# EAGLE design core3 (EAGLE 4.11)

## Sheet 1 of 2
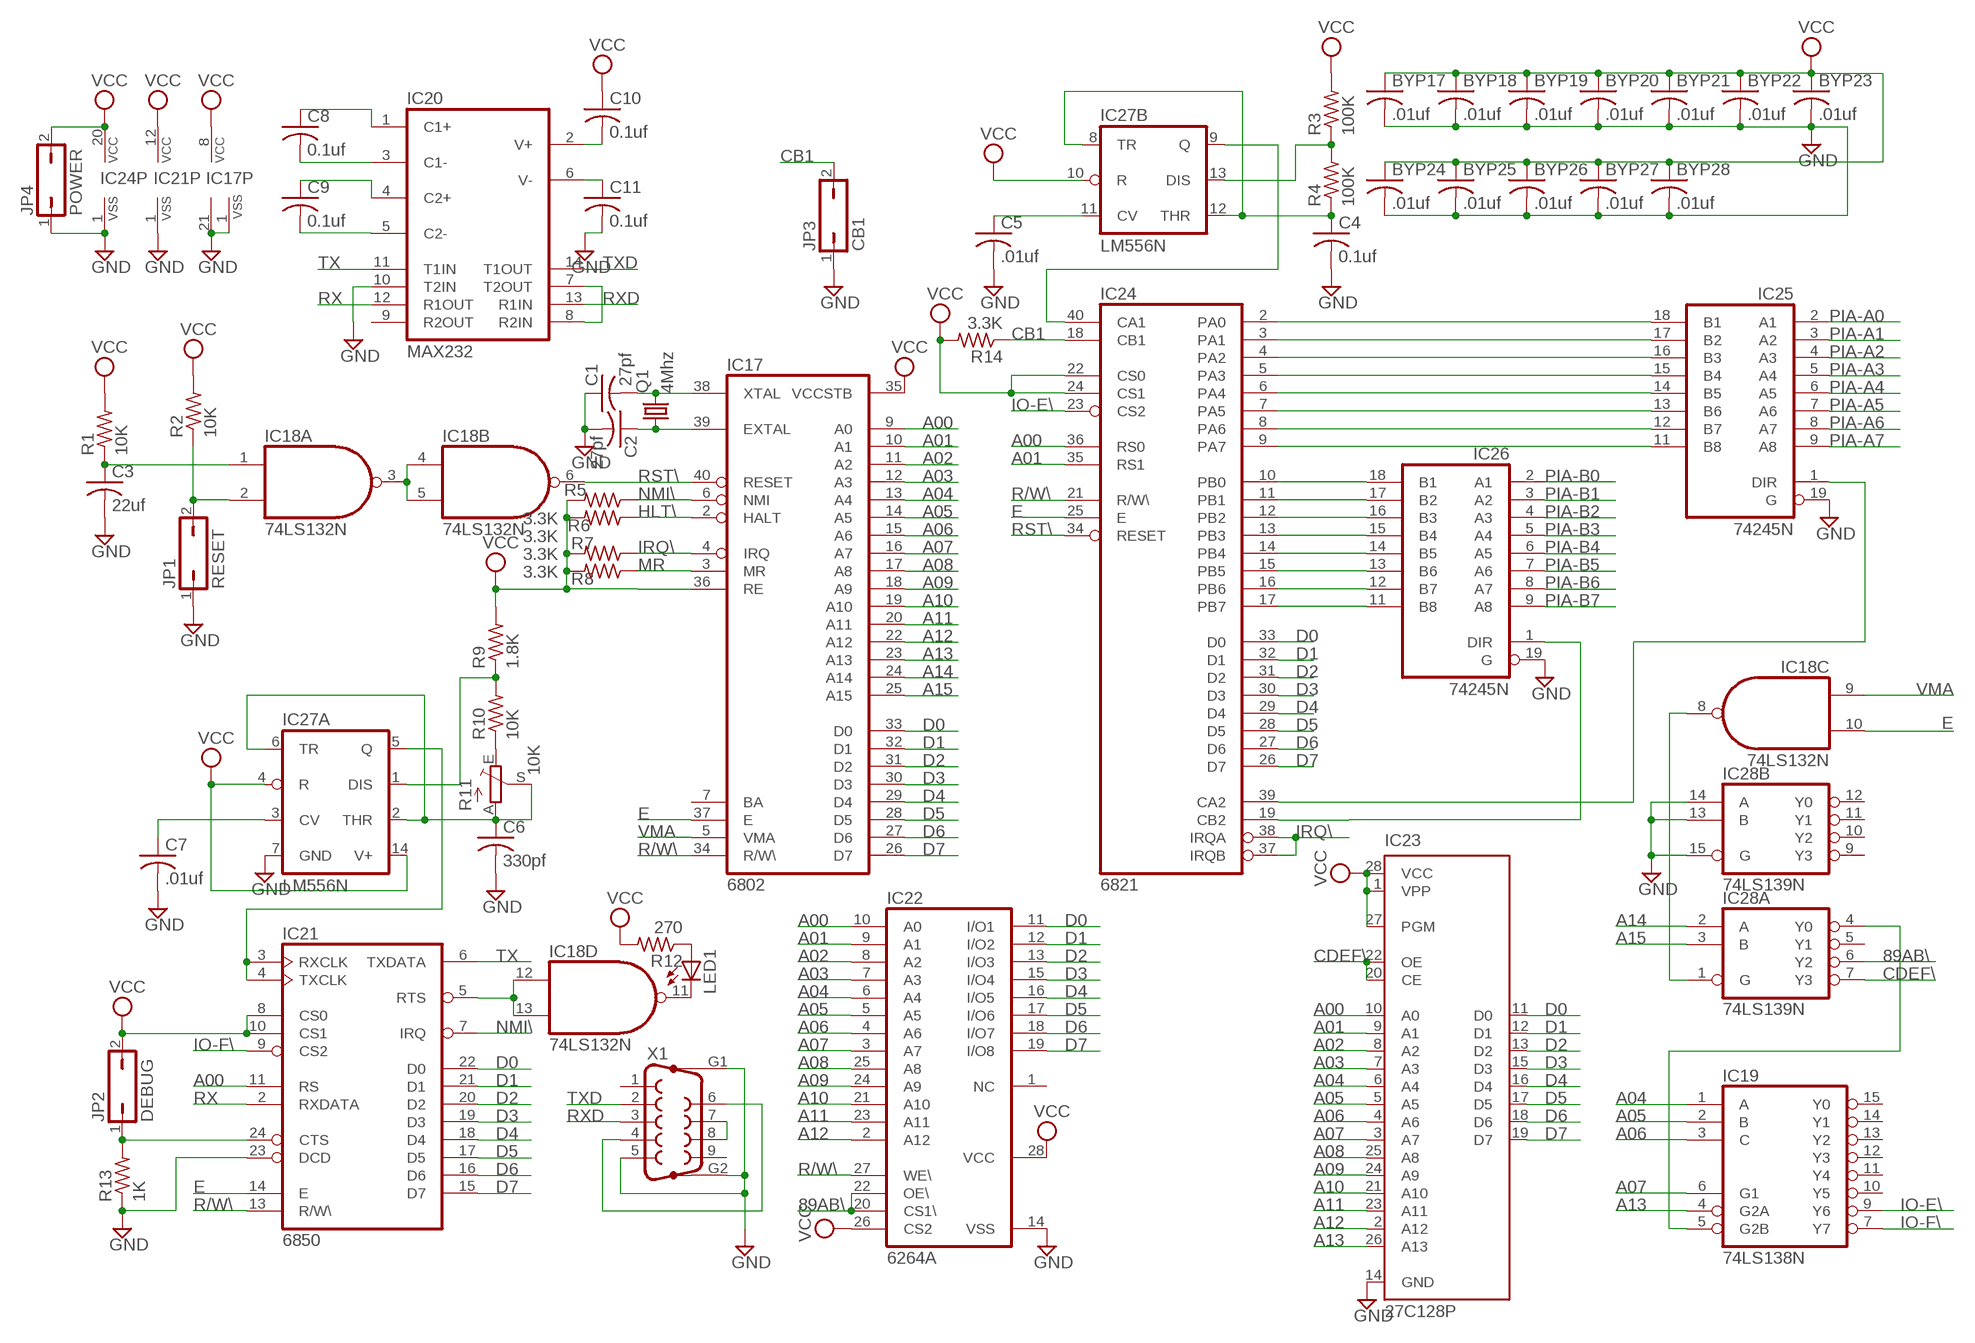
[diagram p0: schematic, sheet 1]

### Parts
BYP17  .01uf  C-US050-025X075  [C050-025X075]
BYP18  .01uf  C-US050-025X075  [C050-025X075]
BYP19  .01uf  C-US050-025X075  [C050-025X075]
BYP20  .01uf  C-US050-025X075  [C050-025X075]
BYP21  .01uf  C-US050-025X075  [C050-025X075]
BYP22  .01uf  C-US050-025X075  [C050-025X075]
BYP23  .01uf  C-US050-025X075  [C050-025X075]
BYP24  .01uf  C-US050-025X075  [C050-025X075]
BYP25  .01uf  C-US050-025X075  [C050-025X075]
BYP26  .01uf  C-US050-025X075  [C050-025X075]
BYP27  .01uf  C-US050-025X075  [C050-025X075]
BYP28  .01uf  C-US050-025X075  [C050-025X075]
C1  27pf  C-US050-025X075  [C050-025X075]
C2  27pf  C-US050-025X075  [C050-025X075]
C3  22uf  C-US102-043X133  [C102-043X133]
C4  0.1uf  C-US050-025X075  [C050-025X075]
C5  .01uf  C-US050-025X075  [C050-025X075]
C6  330pf  C-US050-025X075  [C050-025X075]
C7  .01uf  C-US050-025X075  [C050-025X075]
C8  0.1uf  C-US050-025X075  [C050-025X075]
C9  0.1uf  C-US050-025X075  [C050-025X075]
C10  0.1uf  C-US050-025X075  [C050-025X075]
C11  0.1uf  C-US050-025X075  [C050-025X075]
IC17  6802  [DIL40]
IC18  74LS132N  74LS00N  [DIL14]
IC19  74LS138N  [DIL16]
IC20  MAX232  [DIL16]
IC21  6850  [DIL24]
IC22  6264A  [DIL28-6]
IC23  27C128P  [DIL28-6]
IC24  6821  [DIL40]
IC25  74245N  74LS245N  [DIL20]
IC26  74245N  74LS245N  [DIL20]
IC27  LM556N  [DIL14]
IC28  74LS139N  [DIL16]
JP1  RESET  JP1Q  [JP1]
JP2  DEBUG  JP1Q  [JP1]
JP3  CB1  JP1Q  [JP1]
JP4  POWER  JP1Q  [JP1]
LED1  LED3MM  [LED3MM]
Q1  4Mhz  CRYTALHC18U-V  [HC18U-V]
R1  10K  R-US_0207/7  [0207/7]
R2  10K  R-US_0207/7  [0207/7]
R3  100K  R-US_0207/7  [0207/7]
R4  100K  R-US_0207/7  [0207/7]
R5  3.3K  R-US_0207/7  [0207/7]
R6  3.3K  R-US_0207/7  [0207/7]
R7  3.3K  R-US_0207/7  [0207/7]
R8  3.3K  R-US_0207/7  [0207/7]
R9  1.8K  R-US_0207/7  [0207/7]
R10  10K  R-US_0207/7  [0207/7]
R11  10K  TRIM_EU-B90P  [SP19L]
R12  270  R-US_0207/7  [0207/7]
R13  1K  R-US_0207/7  [0207/7]
R14  3.3K  R-US_0207/7  [0207/7]
X1  F09HP  [F09HP]

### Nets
89AB\: IC22.20(CS1\) IC22.22(OE\) IC28.6(A:Y2)
A00: IC17.9(A0) IC21.11(RS) IC22.10(A0) IC23.10(A0) IC24.36(RS0)
A01: IC17.10(A1) IC22.9(A1) IC23.9(A1) IC24.35(RS1)
A02: IC17.11(A2) IC22.8(A2) IC23.8(A2)
A03: IC17.12(A3) IC22.7(A3) IC23.7(A3)
A04: IC17.13(A4) IC19.1(A) IC22.6(A4) IC23.6(A4)
A05: IC17.14(A5) IC19.2(B) IC22.5(A5) IC23.5(A5)
A06: IC17.15(A6) IC19.3(C) IC22.4(A6) IC23.4(A6)
A07: IC17.16(A7) IC19.6(G1) IC22.3(A7) IC23.3(A7)
A08: IC17.17(A8) IC22.25(A8) IC23.25(A8)
A09: IC17.18(A9) IC22.24(A9) IC23.24(A9)
A10: IC17.19(A10) IC22.21(A10) IC23.21(A10)
A11: IC17.20(A11) IC22.23(A11) IC23.23(A11)
A12: IC17.22(A12) IC22.2(A12) IC23.2(A12)
A13: IC17.23(A13) IC19.4(G2A) IC23.26(A13)
A14: IC17.24(A14) IC28.2(A:A)
A15: IC17.25(A15) IC28.3(A:B)
CB1: IC24.18(CB1) JP3.2 R14.1
CDEF\: IC23.20(CE) IC23.22(OE) IC28.7(A:Y3)
D0: IC17.33(D0) IC21.22(D0) IC22.11(I/O1) IC23.11(D0) IC24.33(D0)
D1: IC17.32(D1) IC21.21(D1) IC22.12(I/O2) IC23.12(D1) IC24.32(D1)
D2: IC17.31(D2) IC21.20(D2) IC22.13(I/O3) IC23.13(D2) IC24.31(D2)
D3: IC17.30(D3) IC21.19(D3) IC22.15(I/O4) IC23.15(D3) IC24.30(D3)
D4: IC17.29(D4) IC21.18(D4) IC22.16(I/O5) IC23.16(D4) IC24.29(D4)
D5: IC17.28(D5) IC21.17(D5) IC22.17(I/O6) IC23.17(D5) IC24.28(D5)
D6: IC17.27(D6) IC21.16(D6) IC22.18(I/O7) IC23.18(D6) IC24.27(D6)
D7: IC17.26(D7) IC21.15(D7) IC22.19(I/O8) IC23.19(D7) IC24.26(D7)
E: IC17.37(E) IC18.10(C:I1) IC21.14(E) IC24.25(E)
GND [Power]: BYP17.2 BYP18.2 BYP19.2 BYP20.2 BYP21.2 BYP22.2 BYP23.2 BYP24.2 BYP25.2 BYP26.2 BYP27.2 BYP28.2 C1.1 C2.2 C3.2 C4.2 C5.2 C6.2 C7.2 C11.2 IC17.1(VSS) IC17.21(VSS) IC20.10(T2IN) IC21.1(VSS) IC21.23(DCD) IC22.14(VSS) IC23.14(GND) IC24.1(VSS) IC25.19(G) IC26.19(G) IC27.7(A:GND) IC28.13(B:B) IC28.14(B:A) IC28.15(B:G) JP1.1 JP3.1 JP4.1 R13.1 X1.5 X1.G1 X1.G2 ; also sheet 2
HLT\: IC17.2(HALT) R5.1
IO-E\: IC19.9(Y6) IC24.23(CS2)
IO-F\: IC19.7(Y7) IC21.9(CS2)
IRQ\: IC17.4(IRQ) IC24.37(IRQB) IC24.38(IRQA) R7.1
MR: IC17.3(MR) R8.1
N$3: C2.1 IC17.39(EXTAL) Q1.1
N$4: C1.2 IC17.38(XTAL) Q1.2
N$5: IC24.2(PA0) IC25.18(B1)
N$6: IC18.3(A:O) IC18.4(B:I0) IC18.5(B:I1)
N$21: C3.1 IC18.1(A:I0) R1.1
N$22: IC18.2(A:I1) JP1.2 R2.1
N$23: IC21.3(RXCLK) IC21.4(TXCLK) IC27.5(A:Q)
N$24: IC24.10(PB0) IC26.18(B1)
N$25: IC24.11(PB1) IC26.17(B2)
N$27: C6.1 IC27.2(A:THR) IC27.6(A:TR) R11.A R11.S
N$28: IC27.1(A:DIS) R9.1 R10.2
N$94: IC24.12(PB2) IC26.16(B3)
N$124: IC24.13(PB3) IC26.15(B4)
N$125: IC24.14(PB4) IC26.14(B5)
N$126: IC24.15(PB5) IC26.13(B6)
N$127: IC24.16(PB6) IC26.12(B7)
N$128: IC24.17(PB7) IC26.11(B8)
N$129: IC24.3(PA1) IC25.17(B2)
N$130: IC24.4(PA2) IC25.16(B3)
N$131: IC24.5(PA3) IC25.15(B4)
N$132: IC24.6(PA4) IC25.14(B5)
N$133: IC24.7(PA5) IC25.13(B6)
N$134: IC24.8(PA6) IC25.12(B7)
N$135: IC24.9(PA7) IC25.11(B8)
N$136: IC24.19(CB2) IC26.1(DIR)
N$137: IC24.39(CA2) IC25.1(DIR)
N$138: IC24.40(CA1) IC27.9(B:Q)
N$140: C4.1 IC27.8(B:TR) IC27.12(B:THR) R4.1
N$141: IC27.13(B:DIS) R3.1 R4.2
N$142: C5.1 IC27.11(B:CV)
N$143: R10.1 R11.E
N$144: X1.4 X1.6
N$145: X1.7 X1.8
N$147: IC18.12(D:I0) IC18.13(D:I1) IC21.5(RTS)
N$148: IC18.11(D:O) LED1.K(C)
N$149: LED1.A R12.1
N$150: IC21.24(CTS) JP2.1 R13.2
N$151: IC18.8(C:O) IC28.1(A:G)
N$152: IC19.5(G2B) IC28.4(A:Y0)
N$153: IC20.7(T2OUT) IC20.8(R2IN)
N$154: C7.1 IC27.3(A:CV)
N$155: C9.2 IC20.5(C2-)
N$156: C9.1 IC20.4(C2+)
N$157: C8.2 IC20.3(C1-)
N$158: C8.1 IC20.1(C1+)
N$159: C11.1 IC20.6(V-)
N$160: C10.2 IC20.2(V+)
NMI\: IC17.6(NMI) IC21.7(IRQ) R6.1
PIA-A0: IC25.2(A1) ; also sheet 2
PIA-A1: IC25.3(A2) ; also sheet 2
PIA-A2: IC25.4(A3) ; also sheet 2
PIA-A3: IC25.5(A4) ; also sheet 2
PIA-A4: IC25.6(A5) ; also sheet 2
PIA-A5: IC25.7(A6) ; also sheet 2
PIA-A6: IC25.8(A7) ; also sheet 2
PIA-A7: IC25.9(A8) ; also sheet 2
PIA-B0: IC26.2(A1) ; also sheet 2
PIA-B1: IC26.3(A2) ; also sheet 2
PIA-B2: IC26.4(A3) ; also sheet 2
PIA-B3: IC26.5(A4) ; also sheet 2
PIA-B4: IC26.6(A5) ; also sheet 2
PIA-B5: IC26.7(A6) ; also sheet 2
PIA-B6: IC26.8(A7) ; also sheet 2
PIA-B7: IC26.9(A8) ; also sheet 2
R/W\: IC17.34(R/W\) IC21.13(R/W\) IC22.27(WE\) IC24.21(R/W\)
RST\: IC17.40(RESET) IC18.6(B:O) IC24.34(RESET)
RX: IC20.12(R1OUT) IC21.2(RXDATA)
RXD: IC20.13(R1IN) X1.3
TX: IC20.11(T1IN) IC21.6(TXDATA)
TXD: IC20.14(T1OUT) X1.2
VCC [Power]: BYP17.1 BYP18.1 BYP19.1 BYP20.1 BYP21.1 BYP22.1 BYP23.1 BYP24.1 BYP25.1 BYP26.1 BYP27.1 BYP28.1 C10.1 IC17.8(VCC) IC17.35(VCCSTB) IC17.36(RE) IC21.8(CS0) IC21.10(CS1) IC21.12(VCC) IC22.26(CS2) IC22.28(VCC) IC23.1(VPP) IC23.27(PGM) IC23.28(VCC) IC24.20(VCC) IC24.22(CS0) IC24.24(CS1) IC27.4(A:R) IC27.10(B:R) IC27.14(A:V+) JP2.2 JP4.2 R1.2 R2.2 R3.2 R5.2 R6.2 R7.2 R8.2 R9.2 R12.2 R14.2 ; also sheet 2
VMA: IC17.5(VMA) IC18.9(C:I0)
Unconnected: IC17.7(BA) IC19.10(Y5) IC19.11(Y4) IC19.12(Y3) IC19.13(Y2) IC19.14(Y1) IC19.15(Y0) IC20.9(R2OUT) IC22.1(NC) IC28.5(A:Y1) IC28.9(B:Y3) IC28.10(B:Y2) IC28.11(B:Y1) IC28.12(B:Y0) X1.1 X1.9

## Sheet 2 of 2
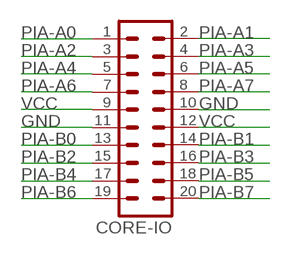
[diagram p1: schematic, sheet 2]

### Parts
CORE-IO  MA10-2  [MA10-2]

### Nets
GND [Power]: CORE-IO.10 CORE-IO.11 ; also sheet 1
PIA-A0: CORE-IO.1 ; also sheet 1
PIA-A1: CORE-IO.2 ; also sheet 1
PIA-A2: CORE-IO.3 ; also sheet 1
PIA-A3: CORE-IO.4 ; also sheet 1
PIA-A4: CORE-IO.5 ; also sheet 1
PIA-A5: CORE-IO.6 ; also sheet 1
PIA-A6: CORE-IO.7 ; also sheet 1
PIA-A7: CORE-IO.8 ; also sheet 1
PIA-B0: CORE-IO.13 ; also sheet 1
PIA-B1: CORE-IO.14 ; also sheet 1
PIA-B2: CORE-IO.15 ; also sheet 1
PIA-B3: CORE-IO.16 ; also sheet 1
PIA-B4: CORE-IO.17 ; also sheet 1
PIA-B5: CORE-IO.18 ; also sheet 1
PIA-B6: CORE-IO.19 ; also sheet 1
PIA-B7: CORE-IO.20 ; also sheet 1
VCC [Power]: CORE-IO.9 CORE-IO.12 ; also sheet 1

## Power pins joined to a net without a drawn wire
GND: IC18.7(P:GND) IC19.8(GND) IC20.15(GND) IC25.10(GND) IC26.10(GND) IC28.8(P:GND)
VCC: IC18.14(P:VCC) IC19.16(VCC) IC20.16(VCC) IC25.20(VCC) IC26.20(VCC) IC28.16(P:VCC)

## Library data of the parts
BYP17-BYP28 C1-C11 = rcl:C-US: CAPACITOR, American symbol
CORE-IO = con-lstb:MA10-2: PIN HEADER
IC17 = micro-motorola:6802: MICROCONTROLLER/MEMORY DEVICE
IC18 = 74xx-us:74*00: Quad 2-input NAND gate
IC19 = 74xx-us:74*138: 3-line to 8-line DECODER/DEMULTIPLEXER
IC20 = maxim:MAX232: RS232 TRANSEIVER
IC21 = micro-motorola:6850: MICROCONTROLLER/MEMORY DEVICE
IC22 = memory-hitachi:6264A: MEMORY
IC23 = microchip:27*128: CMOS EPROM 128 K (16 K x 8)
IC24 = micro-motorola:6821: MICROCONTROLLER/MEMORY DEVICE
IC25 IC26 = 74xx-us:74*245: Octal BUS TRANSCEIVER, 3-state
IC27 = linear:*556: Dual TIMER
IC28 = 74xx-us:74*139: Dual 2-line to 4-line DECODER/DEMULTIPLEXER
JP1-JP4 = jumper:JP1Q: JUMPER
LED1 = led:LED: LED
Q1 = crystal:CRYTAL: CRYSTAL
R1-R10 R12-R14 = rcl:R-US_: RESISTOR, American symbol
R11 = pot:TRIM_EU-: POTENTIOMETER
X1 = con-subd:F09HP: SUB-D

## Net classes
1 Power: width 0.508 mm, drill 0.254 mm, clearance 0.254 mm

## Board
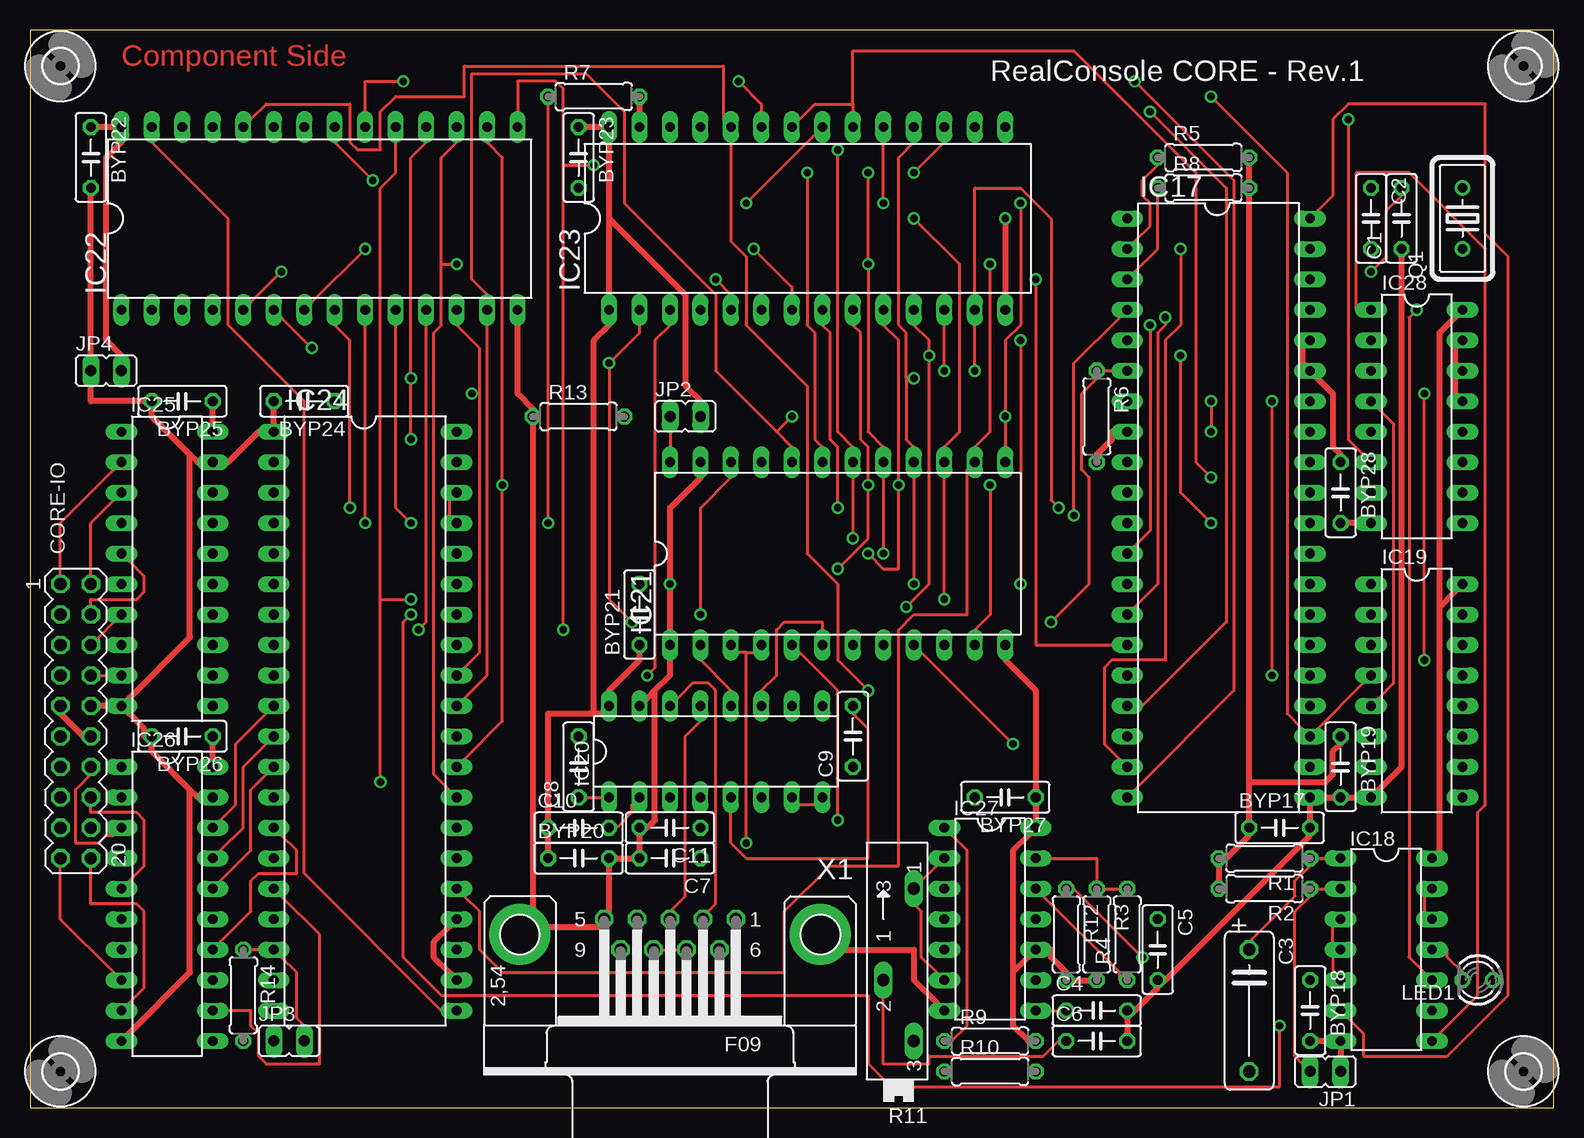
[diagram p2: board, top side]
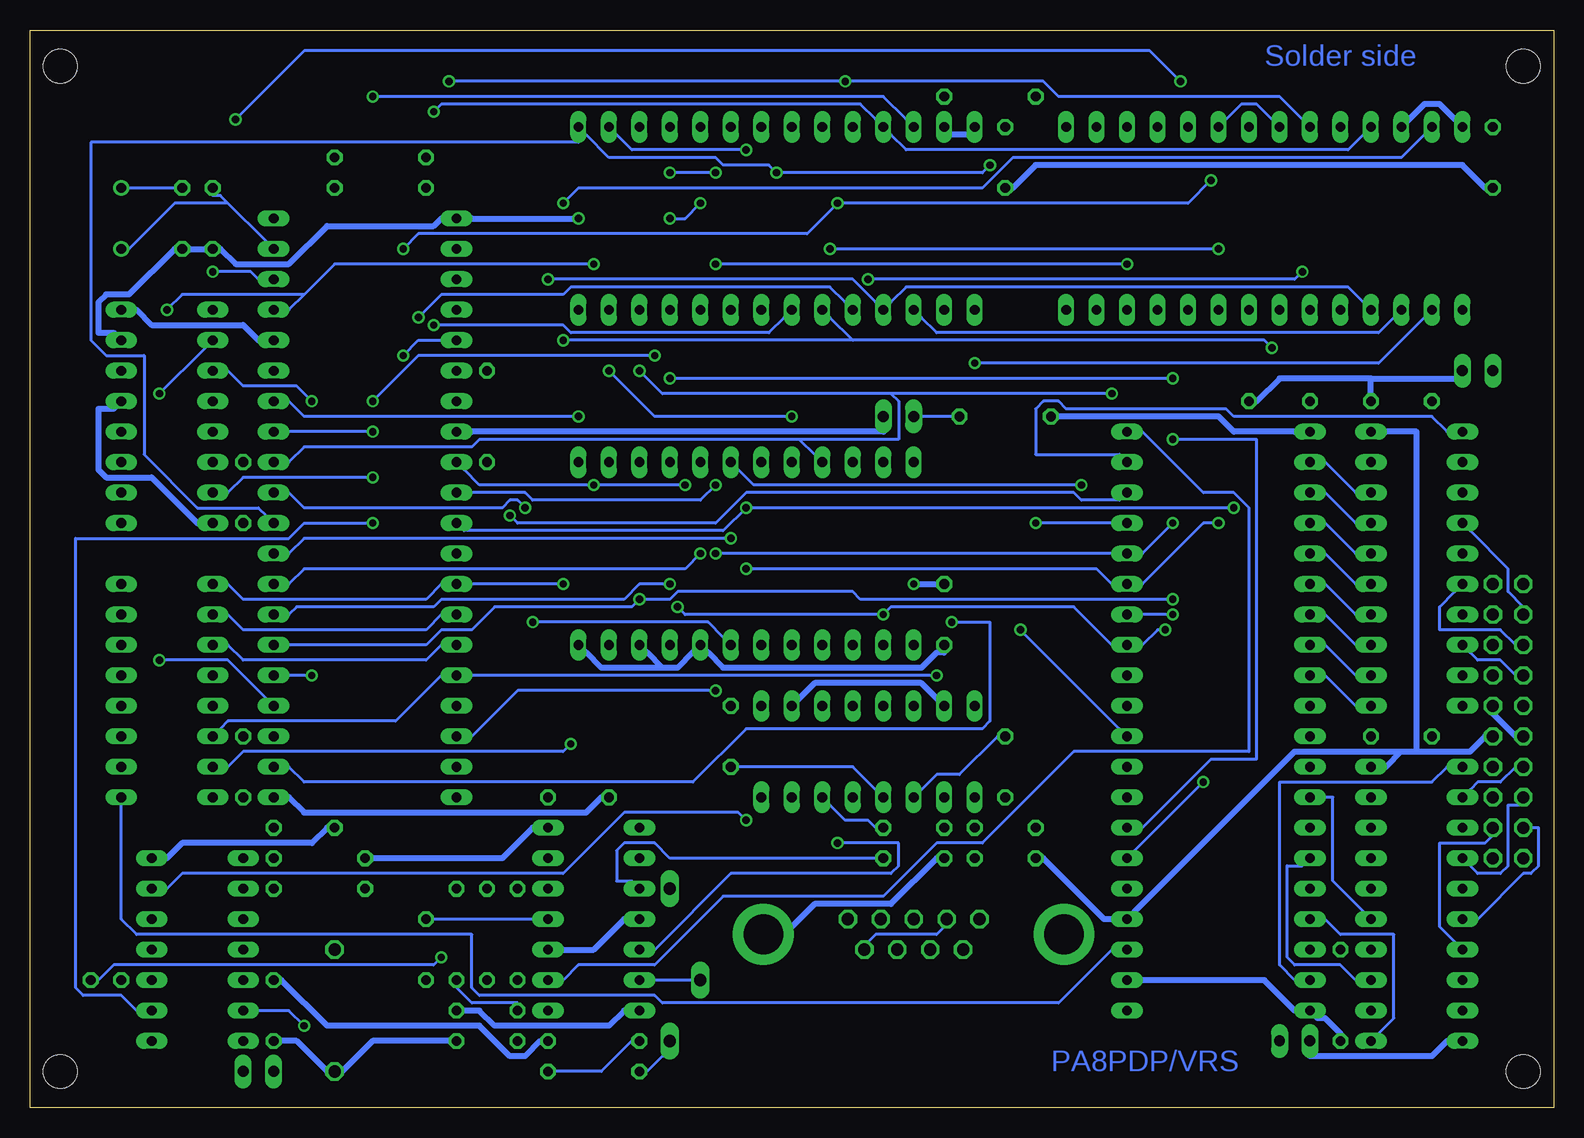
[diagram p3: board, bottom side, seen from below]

Size 126.98 x 89.84 mm. Coordinates in mm from the lower left corner, seen from the top.
Outline: 0,0 126.98,0 126.98,89.84 0,89.84 0,0
Copper layers (1*16): Top 0.035mm / dielectric 1.5mm / Bottom 0.035mm
Design rules "olimex10mil": minimum track width 10mil, minimum drill 24mil, track to track 10mil, track to pad 10mil, pad to pad 10mil, via to via 10mil, smd to smd 10mil, copper to edge 40mil, drill to drill 10mil, minimum pad ring 10mil, minimum via ring 8mil, stop-mask expansion 0mil, vias tented up to drill 0mil, thermal gap 10mil

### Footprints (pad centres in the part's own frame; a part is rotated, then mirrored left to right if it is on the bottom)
C050-025X075 = drill 0.813 octagon: 1 -2.54,0; 2 2.54,0
C102-043X133 = drill 1.016 octagon: 1 -5.08,0; 2 5.08,0
MA10-2 = drill 1.016 octagon: 1 -11.43,-1.27; 2 -11.43,1.27; 3 -8.89,-1.27; 4 -8.89,1.27; 5 -6.35,-1.27; 6 -6.35,1.27; 7 -3.81,-1.27; 8 -3.81,1.27; 9 -1.27,-1.27; 10 -1.27,1.27; 11 1.27,-1.27; 12 1.27,1.27; 13 3.81,-1.27; 14 3.81,1.27; 15 6.35,-1.27; 16 6.35,1.27; 17 8.89,-1.27; 18 8.89,1.27; 19 11.43,-1.27; 20 11.43,1.27
DIL40 = drill 0.813 long: 1 -24.13,-7.62; 2 -21.59,-7.62; 3 -19.05,-7.62; 4 -16.51,-7.62; 5 -13.97,-7.62; 6 -11.43,-7.62; 7 -8.89,-7.62; 8 -6.35,-7.62; 9 -3.81,-7.62; 10 -1.27,-7.62; 11 1.27,-7.62; 12 3.81,-7.62; 13 6.35,-7.62; 14 8.89,-7.62; 15 11.43,-7.62; 16 13.97,-7.62; 17 16.51,-7.62; 18 19.05,-7.62; 19 21.59,-7.62; 20 24.13,-7.62; 21 24.13,7.62; 22 21.59,7.62; 23 19.05,7.62; 24 16.51,7.62; 25 13.97,7.62; 26 11.43,7.62; 27 8.89,7.62; 28 6.35,7.62; 29 3.81,7.62; 30 1.27,7.62; 31 -1.27,7.62; 32 -3.81,7.62; 33 -6.35,7.62; 34 -8.89,7.62; 35 -11.43,7.62; 36 -13.97,7.62; 37 -16.51,7.62; 38 -19.05,7.62; 39 -21.59,7.62; 40 -24.13,7.62
DIL14 = drill 0.813 long: 1 -7.62,-3.81; 2 -5.08,-3.81; 3 -2.54,-3.81; 4 0,-3.81; 5 2.54,-3.81; 6 5.08,-3.81; 7 7.62,-3.81; 8 7.62,3.81; 9 5.08,3.81; 10 2.54,3.81; 11 0,3.81; 12 -2.54,3.81; 13 -5.08,3.81; 14 -7.62,3.81
DIL16 = drill 0.813 long: 1 -8.89,-3.81; 2 -6.35,-3.81; 3 -3.81,-3.81; 4 -1.27,-3.81; 5 1.27,-3.81; 6 3.81,-3.81; 7 6.35,-3.81; 8 8.89,-3.81; 9 8.89,3.81; 10 6.35,3.81; 11 3.81,3.81; 12 1.27,3.81; 13 -1.27,3.81; 14 -3.81,3.81; 15 -6.35,3.81; 16 -8.89,3.81
DIL24 = drill 0.813 long: 1 -13.97,-7.62; 2 -11.43,-7.62; 3 -8.89,-7.62; 4 -6.35,-7.62; 5 -3.81,-7.62; 6 -1.27,-7.62; 7 1.27,-7.62; 8 3.81,-7.62; 9 6.35,-7.62; 10 8.89,-7.62; 11 11.43,-7.62; 12 13.97,-7.62; 13 13.97,7.62; 14 11.43,7.62; 15 8.89,7.62; 16 6.35,7.62; 17 3.81,7.62; 18 1.27,7.62; 19 -1.27,7.62; 20 -3.81,7.62; 21 -6.35,7.62; 22 -8.89,7.62; 23 -11.43,7.62; 24 -13.97,7.62
DIL28-6 = drill 0.813 long: 1 -16.51,-7.62; 2 -13.97,-7.62; 3 -11.43,-7.62; 4 -8.89,-7.62; 5 -6.35,-7.62; 6 -3.81,-7.62; 7 -1.27,-7.62; 8 1.27,-7.62; 9 3.81,-7.62; 10 6.35,-7.62; 11 8.89,-7.62; 12 11.43,-7.62; 13 13.97,-7.62; 14 16.51,-7.62; 15 16.51,7.62; 16 13.97,7.62; 17 11.43,7.62; 18 8.89,7.62; 19 6.35,7.62; 20 3.81,7.62; 21 1.27,7.62; 22 -1.27,7.62; 23 -3.81,7.62; 24 -6.35,7.62; 25 -8.89,7.62; 26 -11.43,7.62; 27 -13.97,7.62; 28 -16.51,7.62
DIL20 = drill 0.813 long: 1 -11.43,-3.81; 2 -8.89,-3.81; 3 -6.35,-3.81; 4 -3.81,-3.81; 5 -1.27,-3.81; 6 1.27,-3.81; 7 3.81,-3.81; 8 6.35,-3.81; 9 8.89,-3.81; 10 11.43,-3.81; 11 11.43,3.81; 12 8.89,3.81; 13 6.35,3.81; 14 3.81,3.81; 15 1.27,3.81; 16 -1.27,3.81; 17 -3.81,3.81; 18 -6.35,3.81; 19 -8.89,3.81; 20 -11.43,3.81
JP1 = drill 0.914 long: 1 0,-1.27; 2 0,1.27
LED3MM = drill 0.813 octagon: A -1.27,0; K 1.27,0
HC18U-V = drill 0.813 round: 1 -2.54,0; 2 2.54,0
0207/7 = drill 0.813 octagon: 1 -3.81,0; 2 3.81,0
SP19L = drill 1.016 long: A 5.715,-1.27; E -6.985,-1.27; S -1.905,1.27
2,8 = hole 2.8: 0,0
F09HP = drill 1.016 octagon: 1 -5.486,-1.27; 2 -2.743,-1.27; 3 0,-1.27; 4 2.743,-1.27; 5 5.486,-1.27; 6 -4.115,1.27; 7 -1.372,1.27; 8 1.372,1.27; 9 4.115,1.27 | drill 3.302 pad 5.08 round: G1 -12.522,0; G2 12.522,0

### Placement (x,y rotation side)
BYP17  104.14,23.33 0 top
BYP18  106.68,8.09 270 top
BYP19  109.22,28.41 270 top
BYP20  45.71,20.79 0 top
BYP21  50.79,41.11 90 top
BYP22  5.08,79.21 270 top
BYP23  45.71,79.21 270 top
BYP24  22.86,58.89 180 top
BYP25  12.69,58.89 180 top
BYP26  12.69,30.95 180 top
BYP27  81.28,25.87 180 top
BYP28  109.22,51.27 270 top
C1  114.3,74.13 90 top
C2  111.76,74.13 270 top
C3  101.59,8.09 270 top
C4  88.9,8.09 0 top
C5  93.98,13.17 270 top
C6  88.9,5.55 0 top
C7  53.34,20.79 180 top
C8  45.71,28.41 90 top
C9  68.58,30.95 90 top
C10  45.71,23.33 0 top
C11  53.34,23.33 180 top
CORE-IO  3.81,32.22 270 top
IC17  99.06,50 270 top
IC18  113.03,13.17 270 top
IC19  115.56,34.76 270 top
IC20  57.14,29.68 0 top
IC21  67.31,46.19 0 top
IC22  24.12,74.13 0 top
IC23  64.77,74.13 0 top
IC24  27.94,32.22 270 top
IC25  11.42,44.92 270 top
IC26  11.42,16.98 270 top
IC27  80.01,15.71 270 top
IC28  115.56,57.62 270 top
JP1  107.95,3.01 90 top
JP2  54.6,57.62 270 top
JP3  21.59,5.55 270 top
JP4  6.34,61.43 270 top
LED1  120.65,10.63 180 top
Q1  119.38,74.13 90 top
R1  102.87,20.79 180 top
R2  102.87,18.25 180 top
R3  88.9,14.44 270 top
R4  91.44,14.44 90 top
R5  97.79,79.21 0 top
R6  88.9,57.62 270 top
R7  46.98,84.29 0 top
R8  97.79,76.67 0 top
R9  80.01,5.55 0 top
R10  80.01,3.01 0 top
R11  72.39,12.54 90 top
R12  86.36,14.44 270 top
R13  45.71,57.62 0 top
R14  17.78,9.36 270 top
U$3  [2,8]  2.54,86.83 0 top
U$4  [2,8]  2.54,3.01 0 top
U$5  [2,8]  124.45,86.83 0 top
U$6  [2,8]  124.45,3.01 0 top
X1  53.34,14.44 180 top

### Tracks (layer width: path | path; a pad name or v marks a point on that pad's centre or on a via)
89AB\  (via drill 0.61)
  Top 0.254: v109.85,82.39 109.85,55.71 111.12,54.45 IC28.6 | v31.11,85.56 27.94,85.56 27.94,83.02 IC22.20
  Bottom 0.254: IC22.22 23.49,82.39 24.76,83.66 26.03,83.66 27.3,82.39 IC22.20 | v109.85,82.39 104.14,88.1 33.65,88.1 v31.11,85.56
A00  (via drill 0.61)
  Top 0.254: v31.75,48.73 30.48,50 30.48,65.24 IC22.10 | v80.01,51.91 80.01,41.11 78.73,39.84 IC21.11 | IC23.10 71.12,65.24 72.39,63.97 v72.39,51.91 72.39,44.92 71.12,44.92 v69.84,46.19
  Bottom 0.254: v31.75,48.73 34.28,46.19 IC24.36 36.82,46.19 v69.84,46.19 | IC17.9 90.8,53.17 89.53,51.91 v80.01,51.91 v72.39,51.91
A01  (via drill 0.61)
  Top 0.254: v27.94,48.73 27.94,65.24 IC22.9 | IC23.9 68.58,65.24 69.21,64.61 69.21,55.71 69.84,55.08 v69.84,51.91 69.84,47.46 v67.31,44.92
  Bottom 0.254: v27.94,48.73 29.21,48.73 34.28,43.65 IC24.35 36.82,43.65 38.09,44.92 v67.31,44.92 | v69.84,51.91 71.12,50.63 85.09,50.63 85.72,51.27 90.17,51.27 IC17.10
A02  (via drill 0.61)
  Top 0.254: v26.67,50 26.67,63.97 25.39,65.24 IC22.8 | v67.31,50 67.31,55.08 66.67,55.71 66.67,64.61 66.04,65.24 IC23.8
  Bottom 0.254: v26.67,50 v67.31,50 69.21,48.09 90.8,48.09 IC17.11
A03  (via drill 0.61)
  Top 0.254: v27.94,71.59 23.49,67.14 IC22.7 | v60.32,71.59 63.49,68.41 63.49,67.78 IC23.7 | v93.34,65.24 93.34,48.09 92.07,46.82 IC17.12
  Bottom 0.254: v27.94,71.59 v60.32,71.59 | v93.34,65.24 82.55,65.24 81.91,64.61 65.4,64.61 64.13,65.88 IC23.7
A04  (via drill 0.61)
  Top 0.254: v23.49,63.34 20.95,65.88 IC22.6 | v82.55,63.97 v82.55,43.65
  Bottom 0.254: IC19.1 110.48,43.65 109.22,42.38 93.98,42.38 92.7,43.65 IC17.13 90.17,43.65 v82.55,43.65 | v23.49,63.34 24.12,63.97 58.41,63.97 | 58.41,63.97 60.32,65.88 IC23.6 | 58.41,63.97 v82.55,63.97
A05  (via drill 0.61)
  Top 0.254: v20.95,69.69 18.41,67.14 IC22.5 | v57.14,69.05 58.41,67.78 IC23.5 | v94.61,65.88 94.61,65.24 93.98,64.61 93.98,43.65 92.07,41.74 IC17.14
  Bottom 0.254: IC17.14 92.7,41.11 93.98,39.84 109.22,39.84 110.48,41.11 IC19.2 | v20.95,69.69 21.59,69.05 v57.14,69.05 | v94.61,65.88 92.7,67.78 82.55,67.78 81.91,68.41 60.32,68.41 59.05,67.14 IC23.5
A06  (via drill 0.61)
  Top 0.254: v83.81,69.05 83.81,38.57 90.17,38.57 IC17.15
  Bottom 0.254: IC17.15 92.7,38.57 93.98,37.3 109.22,37.3 110.48,38.57 IC19.3 | IC22.4 15.87,67.14 17.14,68.41 53.97,68.41 55.24,67.14 IC23.4 56.51,67.14 58.41,69.05 v83.81,69.05
A07  (via drill 0.61)
  Top 0.254: v51.43,36.03 52.06,36.66 52.06,63.97 53.34,65.24 IC23.3
  Bottom 0.254: IC19.6 111.12,31.58 110.48,32.22 96.52,32.22 92.7,36.03 IC17.16 90.17,36.03 v51.43,36.03 | IC22.3 13.33,65.88 14.6,64.61 51.43,64.61 52.7,65.88 IC23.3
A08  (via drill 0.61)
  Top 0.254: v93.34,83.02 99.69,76.67 99.69,40.48 92.7,33.49 IC17.17
  Bottom 0.254: IC22.25 15.87,81.11 17.14,79.84 53.97,79.84 55.24,81.11 IC23.25 56.51,82.39 57.78,83.66 92.7,83.66 v93.34,83.02
A09  (via drill 0.61)
  Top 0.254: IC22.24 18.41,82.39 19.68,83.66 26.67,83.66 26.67,80.48 27.3,79.84 29.21,79.84 29.21,83.02 30.48,84.29 36.19,84.29 36.19,86.83 57.78,86.83 57.78,82.39 IC23.24 58.41,80.48 58.41,72.22 59.68,70.95 59.68,65.24 64.77,60.16 64.77,46.19 67.31,43.65 67.31,37.3 v69.84,34.76
  Bottom 0.254: v69.84,34.76 86.36,34.76 90.17,30.95 IC17.18
A10  (via drill 0.61)
  Top 0.254: v28.57,77.3 25.39,80.48 IC22.21 | v59.68,75.4 65.4,81.11 IC23.21 | v95.88,71.59 95.88,65.24 94.61,63.97 94.61,37.3 90.17,37.3 89.53,36.66 89.53,30.31 90.8,29.04 IC17.19
  Bottom 0.254: v28.57,77.3 30.48,75.4 v59.68,75.4 62.22,72.86 94.61,72.86 v95.88,71.59
A11  (via drill 0.61)
  Top 0.254: v59.05,85.56 60.95,83.66 60.95,83.02 IC23.23 | v92.07,85.56 100.33,77.3 100.33,34.76 92.07,26.5 IC17.20
  Bottom 0.254: IC22.23 20.95,82.39 22.86,84.29 41.27,84.29 42.54,85.56 v59.05,85.56 v92.07,85.56
A12  (via drill 0.61)
  Top 0.254: IC23.2 50.79,65.24 50.79,64.61 v48.25,62.06 48.25,42.38 v50.16,40.48
  Bottom 0.254: v48.25,62.06 14.6,62.06 10.79,65.88 IC22.2 | v50.16,40.48 46.98,40.48 46.98,32.22 47.62,31.58 67.31,31.58 71.75,27.14 104.14,27.14 105.41,28.41 IC17.22
A13  (via drill 0.61)
  Top 0.254: v98.42,84.29 104.77,77.94 104.77,32.85 106.04,31.58 IC17.23 107.31,31.58 111.12,35.39 IC19.4
  Bottom 0.254: v98.42,84.29 55.88,84.29 53.97,82.39 IC23.26
A14  (via drill 0.61)
  Top 0.254: v116.2,37.3 v116.2,59.52
  Bottom 0.254: v116.2,37.3 110.48,37.3 107.31,34.12 IC17.24 | v116.2,59.52 112.39,63.34 IC28.2
A15  (via drill 0.61)
  Top 0.254: v103.5,36.03 v103.5,58.89
  Bottom 0.254: v103.5,36.03 105.41,36.03 IC17.25 | v103.5,58.89 104.77,60.16 109.22,60.16 110.48,61.43 IC28.3
CB1
  Top 0.254: R14.1 18.41,13.17 19.05,13.17 IC24.18 20.95,12.54 22.22,11.27 22.22,7.46 22.86,6.82 JP3.2
CDEF\  (via drill 0.61)
  Top 0.254: 68.58,83.66 65.4,83.66 64.13,82.39 IC23.22 | 68.58,83.66 68.58,83.02 IC23.20 | v98.42,52.54 97.15,53.81 97.15,77.94 86.99,88.1 68.58,88.1 68.58,83.66
  Bottom 0.254: v98.42,52.54 109.22,52.54 110.48,51.27 IC28.7
D0  (via drill 0.61)
  Top 0.254: v32.38,39.84 33.02,40.48 33.02,65.24 IC22.11 | v55.88,41.11 55.88,50 58.41,52.54 IC21.22 | v73.02,41.74 74.93,43.65 v74.93,62.7 74.93,63.97 73.66,65.24 IC23.11 | v98.42,58.89 v98.42,56.35
  Bottom 0.254: v32.38,39.84 33.02,39.84 34.28,38.57 IC24.33 36.82,38.57 40,41.74 55.24,41.74 v55.88,41.11 72.39,41.11 v73.02,41.74 | v98.42,56.35 105.41,56.35 IC17.33 | v98.42,58.89 94.61,62.7 v74.93,62.7
D1  (via drill 0.61)
  Top 0.254: 37.46,59.52 37.46,63.34 35.55,65.24 IC22.12 | 37.46,59.52 37.46,37.94 36.19,36.66 IC24.32 | v76.2,61.43 76.2,65.24 IC23.12 | 37.46,59.52 v36.82,59.52
  Bottom 0.254: 62.86,55.71 61.59,54.45 IC21.21 | 62.86,55.71 89.53,55.71 90.17,55.08 104.14,55.08 105.41,53.81 IC17.32 | v76.2,61.43 74.29,59.52 55.24,59.52 | 55.24,59.52 54.6,58.89 54.6,55.71 62.86,55.71 | v36.82,59.52 55.24,59.52
D2  (via drill 0.61)
  Top 0.254: IC24.31 36.19,34.12 38.09,36.03 38.09,65.24 IC22.13 38.09,67.78 36.82,69.05 36.82,86.19 46.35,86.19 49.52,83.02 49.52,75.4 57.14,67.78 57.14,61.43 62.22,56.35 | 62.22,56.35 63.49,55.08 IC21.20 | v78.73,61.43 78.73,65.24 IC23.13 78.73,67.78 78.73,76.67 82.55,76.67 85.09,74.13 85.09,50.63 v85.72,50 | 62.22,56.35 v63.49,57.62
  Bottom 0.254: v78.73,61.43 74.93,57.62 v63.49,57.62 | v85.72,50 86.36,50.63 86.99,50.63 87.62,50 104.14,50 105.41,51.27 IC17.31
D3  (via drill 0.61)
  Top 0.254: 44.45,78.58 44.45,84.92 43.81,85.56 40.63,85.56 40.63,83.02 IC22.15 | v44.45,39.84 44.45,78.58 | v64.77,77.94 64.77,65.24 65.4,64.61 65.4,55.71 66.04,55.08 IC21.19 | 44.45,78.58 v46.98,78.58
  Bottom 0.254: v44.45,39.84 36.19,31.58 IC24.30 | IC17.30 107.31,49.37 107.95,50 113.03,50 117.47,54.45 117.47,62.7 120.65,62.7 121.92,63.97 121.92,80.48 81.28,80.48 IC23.15 80.64,81.11 78.73,79.21 69.84,79.21 69.21,78.58 65.4,78.58 v64.77,77.94 47.62,77.94 v46.98,78.58
D4  (via drill 0.61)
  Top 0.254: IC24.29 36.19,29.04 39.36,32.22 v39.36,51.91 39.36,79.21 38.09,80.48 IC22.16 | v68.58,47.46 68.58,52.54 IC21.18 68.58,55.08 67.31,56.35 v67.31,79.84
  Bottom 0.254: v39.36,51.91 66.67,51.91 67.94,53.17 IC21.18 | v68.58,47.46 104.14,47.46 105.41,46.19 IC17.29 | v67.31,79.84 76.83,79.84 78.1,81.11 IC23.16
D5  (via drill 0.61)
  Top 0.254: 34.28,70.32 34.28,79.21 35.55,80.48 IC22.17 | 34.28,70.32 34.28,65.24 33.65,64.61 33.65,27.77 34.92,26.5 IC24.28 | v71.12,46.19 71.12,52.54 IC21.17 71.12,55.08 69.84,56.35 v69.84,70.32 v69.84,77.94 | v73.66,77.94 76.2,80.48 IC23.17 | 34.28,70.32 v35.55,70.32
  Bottom 0.254: v71.12,46.19 72.39,44.92 104.14,44.92 105.41,43.65 IC17.28 | v69.84,77.94 v73.66,77.94 | v35.55,70.32 v69.84,70.32
D6  (via drill 0.61)
  Top 0.254: v31.75,55.71 v31.75,60.8 31.75,79.21 33.02,80.48 IC22.18 | 73.02,60.8 73.02,64.61 72.39,65.24 72.39,79.21 73.66,80.48 IC23.18 | 73.02,60.8 73.02,55.71 73.66,55.08 IC21.16 73.66,52.54 v73.66,43.65 | v73.66,60.8 73.02,60.8
  Bottom 0.254: v31.75,55.71 24.76,55.71 24.76,29.04 28.57,29.04 34.28,23.33 IC24.27 | v73.66,43.65 76.2,43.65 77.47,42.38 92.7,42.38 93.34,41.74 104.77,41.74 105.41,41.11 IC17.27 | v31.75,60.8 v73.66,60.8
D7  (via drill 0.61)
  Top 0.254: 29.21,42.38 29.21,76.67 30.48,77.94 30.48,80.48 IC22.19 | v29.21,27.14 29.21,42.38 | v76.2,42.38 76.2,52.54 IC21.15 76.2,55.08 77.47,56.35 77.47,70.32 v73.66,74.13 | v71.12,75.4 71.12,80.48 IC23.19 | 29.21,42.38 v31.75,42.38
  Bottom 0.254: v29.21,27.14 34.92,21.42 IC24.26 | IC17.26 105.41,38.57 93.98,38.57 92.7,39.84 90.17,39.84 88.26,41.74 76.83,41.74 v76.2,42.38 73.66,42.38 73.02,43.02 58.41,43.02 57.78,42.38 v31.75,42.38 | v71.12,75.4 72.39,74.13 v73.66,74.13
E  (via drill 0.61)
  Top 0.254: IC24.25 36.19,17.61 37.46,16.34 37.46,13.17 39.36,11.27 62.86,11.27 62.86,16.34 66.67,20.15 72.39,20.15 72.39,39.84 73.66,41.11 78.1,41.11 78.1,53.17 IC21.14 78.73,55.08 80.01,56.35 v80.01,70.32 | v115.56,66.51 114.93,65.88 114.93,12.54 116.2,11.27 IC18.10
  Bottom 0.254: 104.14,67.78 101.59,70.32 v80.01,70.32 | 104.14,67.78 105.41,66.51 IC17.37 | v115.56,66.51 114.3,67.78 104.14,67.78
GND  (via drill 0.61)
  Top 0.508: IC25.10 6.34,33.49 5.71,33.49 CORE-IO.10 | 13.33,26.5 10.15,29.68 10.15,30.31 BYP26.2 9.52,30.95 9.52,31.58 8.25,32.85 IC25.10 | 13.33,26.5 13.96,25.87 IC26.19 | 13.33,26.5 13.33,11.27 8.25,6.18 IC26.10 | IC22.14 40.63,65.24 40.63,59.52 41.9,58.25 R13.1 41.9,56.98 41.9,16.34 X1.G2 43.17,15.08 47.62,15.08 X1.5 48.25,16.34 48.25,20.15 BYP20.2 48.89,20.79 50.16,20.79 C7.2 50.79,21.42 50.79,22.7 C11.2 51.43,23.33 52.06,23.96 52.06,34.76 | BYP24.2 20.32,58.25 20.32,56.98 IC24.1 19.05,56.35 16.51,53.81 IC25.19 13.96,53.81 13.33,54.45 | BYP22.2 5.08,76.03 5.08,62.7 JP4.1 5.08,60.16 5.08,58.89 9.52,58.89 BYP25.2 10.15,58.25 10.15,57.62 13.33,54.45 | 13.33,54.45 13.33,39.2 8.25,34.12 IC25.10 | 52.06,34.76 53.34,36.03 53.34,37.3 IC21.1 53.34,39.84 v53.34,43.65 53.34,50 55.88,52.54 IC21.23 | 52.06,34.76 51.43,34.12 IC20.15 | v81.28,74.13 81.28,67.78 IC23.14 | BYP28.2 109.85,48.73 110.48,48.73 IC28.8 | IC28.13 118.74,59.52 118.74,60.8 IC28.14 118.74,62.06 118.74,63.34 IC28.15 | BYP18.2 107.31,5.55 107.95,5.55 IC18.7 109.22,4.92 109.22,4.28 JP1.1 | C6.2 91.44,6.18 91.44,7.46 C4.2 92.07,8.09 93.98,10 C5.2 94.61,10.63 106.68,22.7 BYP17.2 106.68,23.96 106.68,25.23 IC17.21 107.95,25.87 108.58,25.87 BYP19.2 109.85,25.87 110.48,25.87 IC19.8 112.39,26.5 114.3,28.41 114.3,70.95 C1.1 | X1.G1 67.94,13.17 73.66,13.17 73.66,10.63 75.56,8.73 IC27.7
  Bottom 0.508: IC26.10 8.88,5.55 10.15,4.28 20.32,4.28 JP3.1 | BYP23.2 45.08,76.67 43.17,78.58 7.62,78.58 5.71,76.67 BYP22.2 | R13.1 41.27,57.62 27.94,57.62 26.67,56.35 21.59,56.35 IC24.1 | v53.34,43.65 51.43,43.65 BYP21.2 | IC20.10 62.86,34.12 61.59,35.39 52.7,35.39 51.43,34.12 IC20.15 | v81.28,74.13 90.17,74.13 IC17.1 92.7,74.13 93.34,73.5 102.23,73.5 105.41,70.32 109.85,70.32 111.12,71.59 C2.2 112.39,71.59 113.66,71.59 C1.1 114.93,71.59 118.74,67.78 120.65,67.78 121.28,67.14 121.28,64.61 120.01,64.61 IC28.15 | IC28.8 113.03,48.73 116.84,52.54 120.65,52.54 121.28,53.17 121.28,58.25 120.01,58.25 IC28.13 | BYP27.2 79.37,25.87 80.64,24.6 104.14,24.6 105.41,25.87 IC17.21 | BYP18.2 106.04,5.55 104.77,5.55 102.23,3.01 C3.2 100.96,3.01 98.42,5.55 92.07,5.55 C6.2 | IC27.7 77.47,8.09 78.73,6.82 88.26,6.82 89.53,8.09 90.8,8.09 C4.2 | C7.2 51.43,20.79 55.24,16.98 61.59,16.98 63.49,15.08 X1.G1 | CORE-IO.11 3.17,30.95 5.08,32.85 CORE-IO.10
HLT\
  Top 0.254: IC17.2 92.07,72.22 93.34,73.5 93.34,75.4 92.7,76.03 92.7,77.3 93.98,78.58 R5.1
IO-E\
  Bottom 0.254: IC24.23 36.82,13.17 41.27,8.73 74.29,8.73 74.93,9.36 89.53,9.36 90.17,10 90.17,14.44 118.11,14.44 119.38,15.71 119.38,25.23 IC19.9
IO-F\  (via drill 0.61)
  Top 0.254: v81.91,30.31 74.29,37.94 IC21.9
  Bottom 0.254: v81.91,30.31 82.55,29.68 109.22,29.68 110.48,28.41 IC19.7
IRQ\  (via drill 0.61)
  Top 0.254: IC24.37 34.92,49.37 34.92,50.63 IC24.38 | v43.17,48.73 43.17,83.66 R7.1 | v86.99,49.37 86.99,62.06 90.8,65.88 IC17.4
  Bottom 0.254: v43.17,48.73 36.82,48.73 IC24.37 | v86.99,49.37 86.36,48.73 69.84,48.73 67.31,51.27 40,51.27 39.36,50.63 36.19,50.63 IC24.38
MR
  Top 0.254: IC17.3 92.07,69.69 93.98,71.59 93.98,76.03 R8.1
N$3
  Bottom 0.254: 110.48,75.4 111.12,76.03 111.76,76.03 C2.1 | 110.48,75.4 107.31,72.22 IC17.39 | 110.48,75.4 114.93,75.4 118.74,71.59 Q1.1
N$4  (via drill 0.61)
  Top 0.254: v111.76,69.69 113.03,70.95 113.03,74.77 114.3,76.03 C1.2
  Bottom 0.254: v111.76,69.69 108.58,69.69 107.95,69.05 IC17.38 | Q1.2 118.74,76.67 114.93,76.67 C1.2
N$5
  Bottom 0.254: IC25.18 16.51,51.27 19.05,53.81 IC24.2
N$6
  Top 0.254: IC18.5 108.58,11.27 108.58,12.54 IC18.4 108.58,13.81 108.58,15.08 IC18.3
N$21
  Top 0.254: IC18.1 107.95,20.79 107.31,20.79 R1.1 106.68,20.15 105.41,18.88 105.41,17.61 101.59,13.81 C3.1
N$22
  Top 0.254: IC18.2 107.95,18.25 107.31,18.25 R2.1 106.68,17.61 105.41,16.34 105.41,4.28 106.04,3.64 JP1.2
N$23  (via drill 0.61)
  Top 0.254: 59.68,37.94 60.32,37.94 IC21.4 | 59.68,37.94 59.05,37.94 IC21.3 | v59.68,22.06 59.68,37.94
  Bottom 0.254: v59.68,22.06 54.6,22.06 54.6,20.15 55.24,19.52 68.58,19.52 74.93,13.17 IC27.5
N$24
  Top 0.254: IC26.18 15.87,23.96 17.14,25.23 17.14,30.31 19.68,32.85 IC24.10
N$25
  Top 0.254: IC26.17 15.87,21.42 17.78,23.33 17.78,28.41 19.68,30.31 IC24.11
N$27
  Top 0.254: IC27.2 75.56,20.15 74.29,18.88 R11.A 73.66,16.98 74.29,16.34 74.29,12.54 75.56,11.27 IC27.6 | C6.1 85.72,5.55 84.45,4.28 74.93,4.28 74.93,3.64 71.12,3.64 71.12,9.36 R11.S
  Bottom 0.254: IC27.6 74.93,10.63 71.75,10.63 R11.S
N$28
  Top 0.254: IC27.1 76.83,22.7 78.1,21.42 78.1,6.82 76.83,5.55 R9.1
  Bottom 0.254: R9.1 76.83,5.55 79.37,3.01 83.18,3.01 R10.2
N$94
  Top 0.254: IC26.16 15.87,18.88 18.41,21.42 18.41,26.5 19.68,27.77 IC24.12
N$124
  Bottom 0.254: IC26.15 15.87,16.34 18.41,18.88 18.41,25.87 19.05,25.87 IC24.13
N$125
  Top 0.254: IC26.14 15.87,13.81 18.41,16.34 18.41,18.88 19.05,19.52 22.22,19.52 22.22,21.42 20.95,22.7 IC24.14
N$126
  Bottom 0.254: IC26.13 16.51,10.63 17.78,11.9 21.59,11.9 22.22,12.54 22.22,20.15 20.95,20.15 IC24.15
N$127
  Top 0.254: IC26.12 16.51,8.09 18.41,8.09 18.41,6.82 19.05,6.18 19.05,4.28 19.68,3.64 24.12,3.64 24.12,14.44 20.95,17.61 IC24.16
N$128
  Bottom 0.254: IC26.11 14.6,6.18 13.33,7.46 13.33,14.44 17.78,14.44 19.05,15.71 IC24.17
N$129
  Bottom 0.254: IC25.17 16.51,48.73 19.05,51.27 IC24.3
N$130
  Bottom 0.254: IC25.16 16.51,46.19 19.05,48.73 IC24.4
N$131
  Bottom 0.254: IC25.15 16.51,43.65 19.05,46.19 IC24.5
N$132
  Bottom 0.254: IC25.14 16.51,41.11 19.05,43.65 IC24.6
N$133
  Bottom 0.254: IC25.13 16.51,38.57 19.05,41.11 IC24.7
N$134
  Bottom 0.254: IC25.12 16.51,36.03 19.05,38.57 IC24.8
N$135
  Bottom 0.254: IC25.11 16.51,33.49 19.05,36.03 IC24.9
N$136
  Bottom 0.254: IC24.19 21.59,10.63 22.86,11.9 22.86,27.14 10.15,27.14 8.88,28.41 IC26.1
N$137
  Bottom 0.254: IC25.1 8.88,56.35 10.15,57.62 26.67,57.62 27.3,58.25 40.63,58.25 41.27,58.89 42.54,58.89 43.17,58.25 43.17,54.45 36.19,54.45 IC24.39
N$138
  Bottom 0.254: IC24.40 34.28,56.35 29.21,51.27 26.67,51.27 25.39,50 25.39,29.68 40,29.68 47.62,22.06 51.43,22.06 55.88,17.61 69.21,17.61 74.93,11.9 81.28,11.9 82.55,10.63 IC27.9
N$140
  Top 0.254: IC27.8 85.09,8.09 85.72,8.09 C4.1 | IC27.12 84.45,17.61 90.8,11.27 90.8,10.63 R4.1
  Bottom 0.254: R4.1 91.44,10 90.17,8.73 86.36,8.73 C4.1
N$141
  Top 0.254: R4.2 90.8,18.25 89.53,18.25 R3.1 88.9,18.88 88.9,20.79 85.09,20.79 IC27.13
N$142
  Bottom 0.254: IC27.11 85.09,15.71 93.34,15.71 C5.1
N$143
  Bottom 0.254: R10.1 75.56,3.01 74.29,4.28 73.66,4.28 R11.E
N$144
  Bottom 0.254: X1.4 50.79,15.08 51.43,14.44 56.51,14.44 57.14,13.81 X1.6
N$145
  Top 0.254: X1.8 52.7,13.17 53.97,13.17 X1.7
N$147  (via drill 0.61)
  Top 0.254: IC18.12 116.2,16.34 116.2,17.61 IC18.13 | v67.31,23.96 67.31,34.76 64.13,37.94 IC21.5
  Bottom 0.254: v67.31,23.96 67.94,24.6 77.47,24.6 82.55,19.52 114.3,19.52 115.56,18.25 IC18.13
N$148
  Top 0.254: LED1.K 119.38,11.27 118.11,12.54 118.11,13.17 IC18.11
N$149  (via drill 0.61)
  Top 0.254: v92.7,12.54 86.99,18.25 R12.1
  Bottom 0.254: v92.7,12.54 93.34,11.9 120.01,11.9 121.28,10.63 LED1.A
N$150
  Top 0.254: IC21.24 53.34,55.08 53.34,56.35 JP2.1
  Bottom 0.254: R13.2 50.16,57.62 52.7,57.62 JP2.1
N$151
  Top 0.254: IC18.8 117.47,6.18 120.65,9.36 120.65,24.6 121.28,25.23 121.28,71.59 114.93,77.94 110.48,77.94 110.48,66.51 IC28.1
N$152
  Top 0.254: IC19.5 112.39,34.12 113.66,35.39 113.66,56.98 112.39,58.25 IC28.4
N$153
  Top 0.254: IC20.7 64.13,25.23 65.4,25.23 IC20.8
N$154
  Bottom 0.254: C7.1 56.51,20.79 73.66,20.79 74.93,22.06 77.47,22.06 78.1,21.42 78.1,18.88 76.83,18.88 IC27.3
N$155
  Top 0.254: IC20.5 58.41,24.6 58.41,22.06 59.68,20.79 69.84,20.79 69.84,31.58 68.58,32.85 C9.2
N$156
  Bottom 0.254: IC20.4 56.51,26.5 58.41,28.41 67.94,28.41 C9.1
N$157
  Bottom 0.254: C8.2 46.35,30.95 49.52,27.77 51.43,27.77 52.7,26.5 IC20.3
N$158
  Top 0.254: C8.1 46.35,25.87 47.62,25.87 IC20.1
N$159
  Bottom 0.254: C11.1 56.51,23.33 57.14,23.96 59.05,23.96 60.32,25.23 IC20.6
N$160
  Top 0.254: C10.2 48.89,23.33 50.16,24.6 50.16,25.23 IC20.2
NMI\  (via drill 0.61)
  Top 0.254: v85.09,40.48 88.26,43.65 88.26,52.54 87.62,53.17 87.62,59.52 88.9,60.8 R6.1 89.53,61.43 90.17,61.43 IC17.6
  Bottom 0.254: v85.09,40.48 70.48,40.48 69.21,39.2 IC21.7
PIA-A0
  Top 0.254: IC25.2 6.98,53.17 2.54,48.73 2.54,44.28 CORE-IO.1
PIA-A1
  Top 0.254: IC25.3 6.98,50.63 5.08,48.73 5.08,44.28 CORE-IO.2
PIA-A2
  Bottom 0.254: IC25.4 6.98,48.09 3.81,44.92 3.81,43.02 2.54,41.74 CORE-IO.3
PIA-A3
  Top 0.254: IC25.5 8.25,45.55 9.52,44.28 9.52,43.02 8.88,42.38 5.08,42.38 5.08,41.74 CORE-IO.4
PIA-A4
  Bottom 0.254: IC25.6 8.25,43.02 9.52,41.74 9.52,39.84 4.44,39.84 3.17,38.57 CORE-IO.5
PIA-A5
  Top 0.254: IC25.7 6.98,40.48 5.71,39.2 5.71,38.57 CORE-IO.6
PIA-A6
  Bottom 0.254: IC25.8 6.98,37.94 6.34,37.3 4.44,37.3 3.17,36.03 CORE-IO.7
PIA-A7
  Top 0.254: IC25.9 6.34,36.03 5.71,36.03 CORE-IO.8
PIA-B0
  Bottom 0.254: IC26.2 6.98,26.5 6.34,27.14 4.44,27.14 3.17,28.41 CORE-IO.13
PIA-B1
  Top 0.254: IC26.3 6.98,22.7 6.34,22.7 5.71,22.06 3.81,22.06 3.81,26.5 5.08,27.77 CORE-IO.14
PIA-B2
  Bottom 0.254: IC26.4 6.98,20.15 6.34,19.52 4.44,19.52 3.81,20.15 3.81,25.23 2.54,25.23 CORE-IO.15
PIA-B3
  Top 0.254: IC26.5 8.25,18.88 9.52,20.15 9.52,23.96 8.88,24.6 5.08,24.6 5.08,25.23 CORE-IO.16
PIA-B4
  Bottom 0.254: IC26.6 6.34,15.71 2.54,19.52 1.9,19.52 1.27,20.15 1.27,23.33 1.9,23.33 CORE-IO.17
PIA-B5
  Bottom 0.254: IC26.7 8.25,13.81 9.52,15.08 9.52,22.06 5.71,22.06 5.08,22.7 CORE-IO.18
PIA-B6
  Top 0.254: IC26.8 6.98,11.27 2.54,15.71 2.54,20.15 CORE-IO.19
PIA-B7
  Top 0.254: IC26.9 8.25,8.73 9.52,10 9.52,16.34 8.88,16.98 5.08,16.98 5.08,20.15 CORE-IO.20
R/W\  (via drill 0.61)
  Top 0.254: IC21.13 81.28,55.08 v81.28,57.62 81.28,63.97 82.55,65.24 v82.55,75.4 | IC24.21 34.28,8.09 22.86,19.52 22.86,58.89 16.51,65.24 16.51,74.13 10.15,80.48 IC22.27
  Bottom 0.254: v81.28,57.62 104.14,57.62 105.41,58.89 IC17.34 | v82.55,75.4 81.28,76.67 47.62,76.67 45.08,79.21 12.69,79.21 10.79,81.11 IC22.27
RST\  (via drill 0.61)
  Top 0.254: v31.75,41.11 31.11,40.48 31.11,12.54 34.28,9.36 69.84,9.36 69.84,3.64 71.75,1.74 104.14,1.74 v104.14,6.82 | IC17.40 107.31,74.77 108.58,76.03 108.58,82.39 109.85,83.66 121.28,83.66 121.28,72.86 123.19,70.95 123.19,9.36 118.11,4.28 111.12,4.28 111.12,6.18 109.85,7.46 IC18.6
  Bottom 0.254: v31.75,41.11 34.28,41.11 IC24.34 | v104.14,6.82 105.41,8.09 107.95,8.09 IC18.6
RX
  Top 0.254: IC20.12 58.41,34.76 55.88,37.3 IC21.2
RXD
  Top 0.254: IC20.13 55.88,32.22 54.6,30.95 54.6,17.61 53.34,16.34 X1.3
TX
  Top 0.254: IC20.11 60.95,34.76 62.22,36.03 62.22,39.84 62.86,40.48 66.04,40.48 66.04,39.84 IC21.6
TXD
  Top 0.254: IC20.14 53.97,34.12 55.24,35.39 56.51,35.39 57.14,34.76 57.14,16.98 56.51,16.34 X1.2
VCC
  Top 0.508: R3.2 88.26,10.63 86.99,10.63 R12.2 86.36,11.27 85.09,12.54 85.09,13.17 IC27.10 83.18,12.54 81.91,11.27 | 81.91,11.27 81.91,6.82 83.18,5.55 R9.2 | 81.91,11.27 81.91,21.42 83.18,22.7 IC27.14 83.81,23.96 83.81,25.23 BYP27.1 83.81,26.5 83.81,34.76 81.28,37.3 IC21.12 | IC17.36 106.04,63.34 106.04,62.06 IC17.35 107.31,60.8 108.58,59.52 108.58,55.08 109.22,54.45 BYP28.1 | R5.2 101.59,78.58 101.59,77.3 R8.2 101.59,76.03 101.59,27.14 | R2.2 99.06,18.88 99.06,20.15 R1.2 99.69,20.79 101.59,22.7 BYP17.1 101.59,23.96 101.59,27.14 | 101.59,27.14 107.95,27.14 108.58,27.77 108.58,29.68 109.22,30.31 BYP19.1 | 117.47,41.74 118.74,43.02 IC19.16 | 117.47,41.74 117.47,21.42 IC18.14 | 117.47,41.74 117.47,64.61 118.74,65.88 IC28.16 | R6.2 88.9,54.45 90.17,55.71 90.17,56.35 IC17.8 | IC23.27 50.79,83.02 50.79,83.66 R7.2 | BYP23.1 46.35,81.75 47.62,81.75 IC23.28 48.25,80.48 48.25,74.13 | 48.25,74.13 48.25,67.78 IC23.1 48.25,65.24 46.98,63.97 46.98,32.85 | 48.25,74.13 54.6,67.78 54.6,60.16 55.88,58.89 JP2.2 | BYP21.1 50.79,37.94 50.79,37.3 48.25,34.76 IC20.16 47.62,32.85 46.98,32.85 | BYP20.1 43.17,21.42 43.17,22.7 C10.1 43.17,23.96 43.17,32.85 46.98,32.85 | IC24.22 34.92,11.27 33.65,12.54 33.65,13.81 34.92,15.08 IC24.24 | IC26.20 15.23,29.04 15.23,30.31 BYP26.1 | BYP22.1 5.71,81.75 6.98,81.75 IC22.28 7.62,80.48 6.34,79.21 6.34,63.97 7.62,62.7 JP4.2 | IC25.20 15.23,56.98 15.23,58.25 BYP25.1 | CORE-IO.9 2.54,32.85 4.44,30.95 CORE-IO.12
  Bottom 0.508: 74.29,36.66 73.02,36.66 71.75,37.94 IC21.8 70.48,37.94 69.21,36.66 52.7,36.66 51.43,37.94 50.79,37.94 BYP21.1 | 74.29,36.66 75.56,37.94 IC21.10 | 74.29,36.66 79.37,36.66 80.64,37.94 IC21.12 | IC27.4 77.47,15.71 80.01,13.17 82.55,13.17 IC27.10 | BYP18.1 106.04,10.63 102.23,6.82 89.53,6.82 86.99,4.28 85.72,4.28 84.45,5.55 R9.2 | IC28.16 118.11,66.51 116.84,65.24 109.22,65.24 107.95,63.97 IC17.36 | IC18.14 115.56,20.79 114.3,22.06 103.5,22.06 102.23,23.33 BYP17.1 | IC27.14 85.09,23.33 87.62,20.79 98.42,20.79 R1.2 | IC23.27 50.16,81.11 48.89,81.11 IC23.28 | IC17.8 90.17,56.35 55.88,56.35 JP2.2 | R14.2 17.78,6.18 19.05,7.46 19.68,7.46 IC24.20 21.59,8.09 24.12,10.63 34.28,10.63 IC24.22 | BYP20.1 42.54,20.79 37.46,15.71 36.82,15.71 IC24.24 34.92,16.34 21.59,29.68 12.69,29.68 | 12.69,29.68 13.96,28.41 IC26.20 | 11.42,29.68 6.98,29.68 5.71,30.95 CORE-IO.12 | 12.69,29.68 11.42,29.68 | IC22.26 12.06,82.39 10.79,83.66 9.52,83.66 8.25,82.39 IC22.28 | 15.23,60.8 8.25,60.8 JP4.2 | 15.23,60.8 22.86,60.8 24.76,58.89 BYP24.1 | 15.23,60.8 15.23,59.52 BYP25.1 | 11.42,29.68 11.42,56.35 13.96,56.35 IC25.20
VMA  (via drill 0.61)
  Top 0.254: v98.42,48.73 95.88,51.27 v95.88,62.7
  Bottom 0.254: v98.42,48.73 104.14,48.73 105.41,47.46 123.19,47.46 123.19,10 122.55,9.36 119.38,9.36 118.11,8.09 IC18.9 | v95.88,62.7 94.61,63.97 92.7,63.97 IC17.5

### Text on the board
Top: Component Side
Bottom: Solder side | PA8PDP/VRS
tPlace: RealConsole CORE - Rev.1 | +
tValues: - | +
